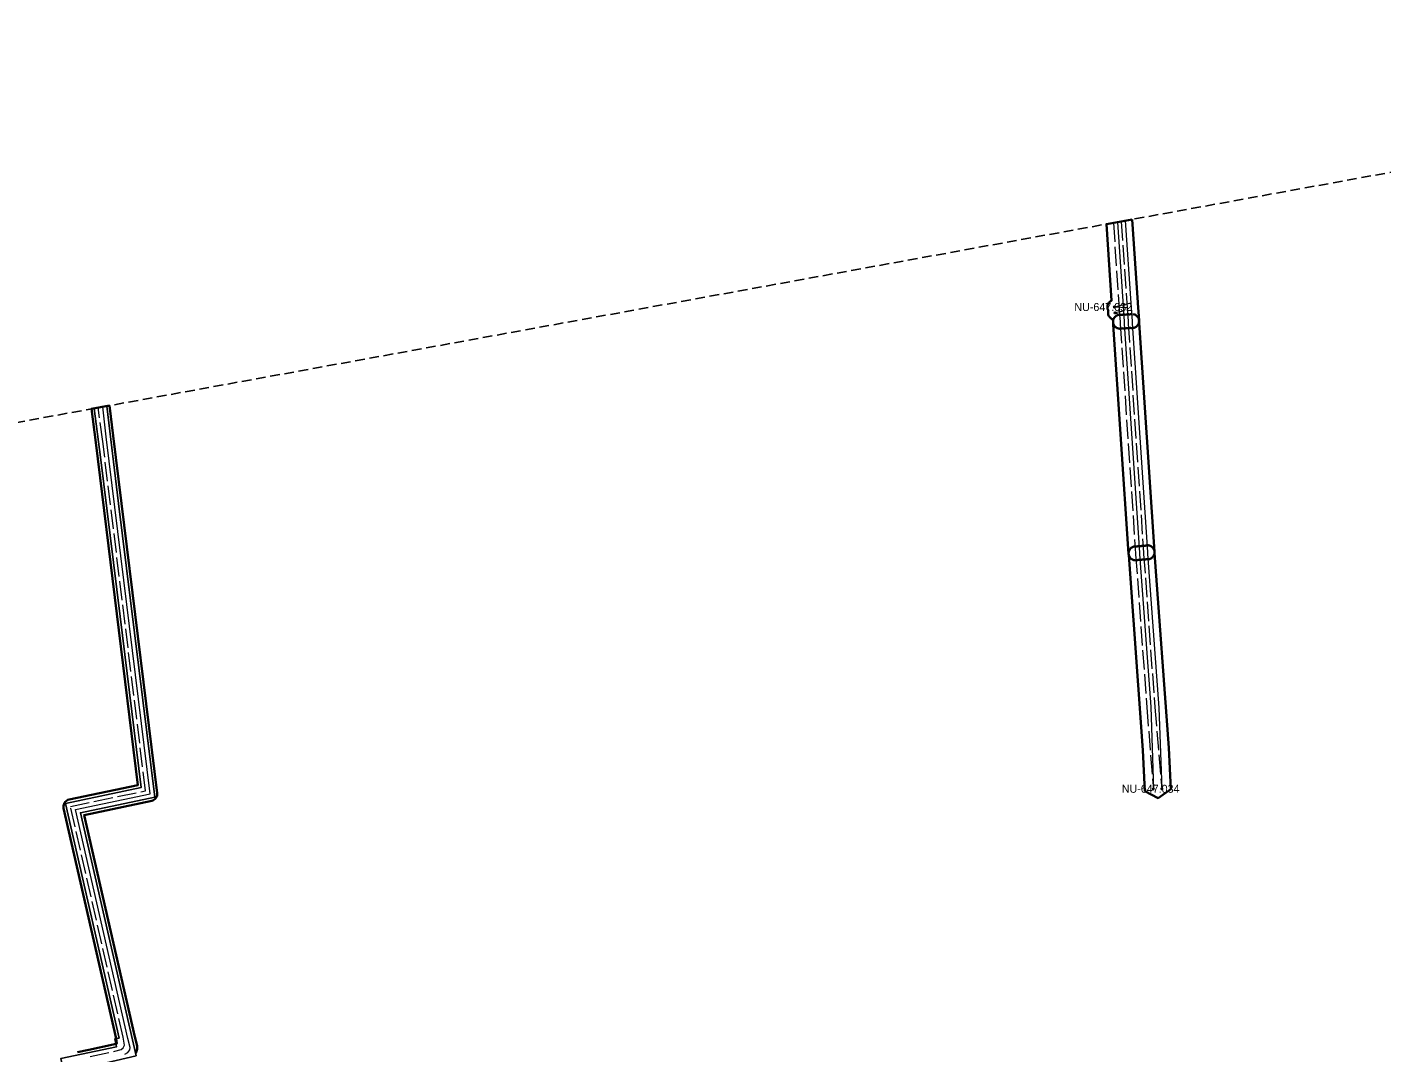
# Model space of a CAD drawing. Extents: x -452602 to -451136, y -1100088 to -1099653.
# Drawn here: x -451916.9 to -451781.4, y -1099858.1 to -1099755.5 of the extents above; entities that cross this region are included whole.
import ezdxf

# ---------------------------------------------------------------- set-up
doc = ezdxf.new("R2010")
doc.units = 0
doc.header["$LTSCALE"] = 0.32
doc.header["$PDMODE"] = 32
doc.header["$PDSIZE"] = 0.16
doc.linetypes.add('LONG_DASHED', pattern=[7.5, 6, -1.5])
doc.linetypes.add('MEDIUM_DASHED', pattern=[4.5, 3, -1.5])
for name, color, linetype, lineweight in [('2', 7, 'Continuous', 13), ('3', 7, 'Continuous', 25), ('62', 7, 'MEDIUM_DASHED', 25), ('8', 7, 'Continuous', 35)]:
    doc.layers.add(name, color=color, linetype=linetype, lineweight=lineweight)
doc.layers.add('4', color=7, linetype='Continuous')

msp = doc.modelspace()

# ---------------------------------------------------------------- linework, layer by layer
at = {"layer": '2', "linetype": 'LONG_DASHED'}
for p, q in [((-451808.262, -1099775.029), (-451807.645, -1099784.223)), ((-451807.469, -1099774.885), (-451806.889, -1099783.532)), ((-451806.889, -1099783.532), (-451808.164, -1099783.454)), ((-451806.889, -1099783.532), (-451806.798, -1099784.881)), ((-451807.645, -1099784.223), (-451808.094, -1099784.032)), ((-451807.645, -1099784.223), (-451807.598, -1099784.925)), ((-451804.925, -1099823.481), (-451804.268, -1099831.67)), ((-451804.124, -1099823.48), (-451803.421, -1099831.643))]:
    msp.add_line(p, q, dxfattribs=at)
at = {"layer": '2'}
for p, q in [((-451807.866, -1099774.957), (-451807.268, -1099783.874)), ((-451807.073, -1099774.813), (-451806.52, -1099783.061)), ((-451806.52, -1099783.061), (-451808.164, -1099783.454)), ((-451806.52, -1099783.061), (-451806.399, -1099784.861)), ((-451807.268, -1099783.874), (-451808.094, -1099784.032)), ((-451807.268, -1099783.874), (-451807.199, -1099784.903)), ((-451804.527, -1099823.448), (-451804.268, -1099831.67)), ((-451803.718, -1099823.551), (-451803.421, -1099831.643))]:
    msp.add_line(p, q, dxfattribs=at)
at = {"layer": '2', "linetype": 'LONG_DASHED'}
for points in [[(-451807.598, -1099784.925), (-451807.583, -1099785.149), (-451806.043, -1099808.094)], [(-451806.798, -1099784.881), (-451806.784, -1099785.096), (-451805.245, -1099808.024)], [(-451910.569, -1099858.433), (-451908.098, -1099857.907), (-451907.453, -1099857.73), (-451907.256, -1099857.548), (-451907.146, -1099857.285), (-451907.281, -1099856.503), (-451912.534, -1099833.415), (-451905.03, -1099831.839), (-451909.305, -1099796.918), (-451909.755, -1099793.518)], [(-451806.043, -1099808.094), (-451806.035, -1099808.217), (-451804.925, -1099823.481)], [(-451805.245, -1099808.024), (-451805.236, -1099808.16), (-451804.124, -1099823.48)]]:
    msp.add_lwpolyline(points, dxfattribs=at)
at = {"layer": '2'}
for points in [[(-451807.199, -1099784.903), (-451807.184, -1099785.122), (-451805.645, -1099808.059)], [(-451806.399, -1099784.861), (-451806.385, -1099785.068), (-451804.847, -1099807.989)], [(-451907.097, -1099858.2), (-451906.807, -1099858.025), (-451906.603, -1099857.741), (-451906.558, -1099857.538), (-451906.795, -1099856.611), (-451912.02, -1099833.732), (-451904.554, -1099832.158), (-451908.958, -1099796.423), (-451909.308, -1099793.436)], [(-451805.645, -1099808.059), (-451805.636, -1099808.188), (-451804.527, -1099823.448)], [(-451804.847, -1099807.989), (-451804.837, -1099808.133), (-451803.718, -1099823.551)]]:
    msp.add_lwpolyline(points, dxfattribs=at)
at = {"layer": '3'}
msp.add_lwpolyline([(-451904.636, -1099869.929), (-451904.863, -1099868.93), (-451906.412, -1099862.297), (-451906.981, -1099862.474), (-451907.181, -1099861.682), (-451912.537, -1099862.903), (-451913.505, -1099858.632), (-451907.928, -1099857.445), (-451908.108, -1099856.664), (-451907.674, -1099856.581), (-451913.014, -1099833.107), (-451905.472, -1099831.523), (-451907.565, -1099814.42), (-451909.516, -1099798.485), (-451910.152, -1099793.59), (-451908.893, -1099793.361), (-451907.732, -1099803.104), (-451904.112, -1099832.473), (-451911.54, -1099834.039), (-451905.974, -1099858.353), (-451911.404, -1099859.633), (-451911.089, -1099860.954), (-451905.594, -1099859.769), (-451903.412, -1099869.624)], close=True, dxfattribs=at)
at = {"layer": '4'}
for p in [(-451808.164, -1099783.454), (-451808.094, -1099784.032), (-451804.268, -1099831.67), (-451803.421, -1099831.643)]:
    msp.add_point(p, dxfattribs=at)
at = {"layer": '62'}
msp.add_lwpolyline([(-451137.485, -1099816.961), (-452572.169, -1100088.267), (-452602.314, -1099919.678), (-451137.485, -1099652.838), (-451136.368, -1099701.963)], close=True, dxfattribs=at)
at = {"layer": '8'}
msp.add_line((-451806.269, -1099784.173), (-451806.197, -1099784.19), dxfattribs=at)
for points in [[(-451806.38, -1099774.687), (-451805.824, -1099782.986), (-451805.822, -1099783.014), (-451805.819, -1099783.06), (-451805.7, -1099784.814), (-451805.699, -1099784.861), (-451805.703, -1099784.935), (-451805.715, -1099785.008), (-451805.734, -1099785.08), (-451805.761, -1099785.15), (-451805.796, -1099785.216), (-451805.837, -1099785.278), (-451805.884, -1099785.335), (-451805.938, -1099785.387), (-451805.996, -1099785.433), (-451806.06, -1099785.473), (-451806.127, -1099785.505), (-451806.197, -1099785.531), (-451806.269, -1099785.548), (-451806.343, -1099785.558), (-451806.417, -1099785.56), (-451806.492, -1099785.554), (-451806.565, -1099785.541), (-451806.596, -1099785.552), (-451806.668, -1099785.569), (-451806.742, -1099785.579), (-451806.816, -1099785.581), (-451806.891, -1099785.575), (-451806.964, -1099785.562), (-451806.997, -1099785.574), (-451807.069, -1099785.591), (-451807.143, -1099785.601), (-451807.217, -1099785.603), (-451807.292, -1099785.597), (-451807.365, -1099785.583), (-451807.396, -1099785.595), (-451807.468, -1099785.612), (-451807.542, -1099785.622), (-451807.616, -1099785.624), (-451807.691, -1099785.618), (-451807.764, -1099785.605), (-451807.835, -1099785.583), (-451807.904, -1099785.554), (-451807.969, -1099785.518), (-451808.03, -1099785.475), (-451808.086, -1099785.426), (-451808.137, -1099785.371), (-451808.181, -1099785.311), (-451808.219, -1099785.247), (-451808.25, -1099785.179), (-451808.273, -1099785.109), (-451808.289, -1099785.036), (-451808.296, -1099784.971), (-451808.314, -1099784.699), (-451808.368, -1099784.676), (-451808.401, -1099784.661), (-451808.466, -1099784.625), (-451808.527, -1099784.582), (-451808.583, -1099784.533), (-451808.633, -1099784.478), (-451808.678, -1099784.418), (-451808.716, -1099784.354), (-451808.746, -1099784.286), (-451808.77, -1099784.216), (-451808.786, -1099784.143), (-451808.793, -1099784.069), (-451808.793, -1099783.994), (-451808.786, -1099783.92), (-451808.77, -1099783.847), (-451808.761, -1099783.82), (-451808.786, -1099783.777), (-451808.816, -1099783.709), (-451808.84, -1099783.639), (-451808.856, -1099783.566), (-451808.864, -1099783.492), (-451808.864, -1099783.417), (-451808.856, -1099783.343), (-451808.84, -1099783.27), (-451808.816, -1099783.2), (-451808.786, -1099783.132), (-451808.748, -1099783.068), (-451808.703, -1099783.008), (-451808.653, -1099782.953), (-451808.597, -1099782.904), (-451808.536, -1099782.861), (-451808.471, -1099782.825), (-451808.441, -1099782.813), (-451808.955, -1099775.156)], [(-451802.725, -1099827.558), (-451802.506, -1099831.679), (-451803.792, -1099832.569), (-451805.109, -1099831.87), (-451805.315, -1099827.774), (-451806.733, -1099808.265), (-451806.741, -1099808.139), (-451806.742, -1099808.131), (-451806.742, -1099808.056), (-451806.734, -1099807.982), (-451806.718, -1099807.909), (-451806.695, -1099807.839), (-451806.664, -1099807.771), (-451806.626, -1099807.706), (-451806.582, -1099807.647), (-451806.531, -1099807.592), (-451806.475, -1099807.543), (-451806.414, -1099807.5), (-451806.349, -1099807.464), (-451806.28, -1099807.435), (-451806.209, -1099807.414), (-451806.136, -1099807.4), (-451806.061, -1099807.394), (-451805.987, -1099807.396), (-451805.913, -1099807.406), (-451805.901, -1099807.409), (-451805.882, -1099807.401), (-451805.811, -1099807.379), (-451805.738, -1099807.366), (-451805.663, -1099807.36), (-451805.589, -1099807.362), (-451805.515, -1099807.372), (-451805.503, -1099807.375), (-451805.482, -1099807.366), (-451805.411, -1099807.344), (-451805.338, -1099807.331), (-451805.263, -1099807.325), (-451805.189, -1099807.327), (-451805.115, -1099807.337), (-451805.104, -1099807.339), (-451805.084, -1099807.331), (-451805.013, -1099807.309), (-451804.94, -1099807.296), (-451804.865, -1099807.29), (-451804.791, -1099807.292), (-451804.717, -1099807.302), (-451804.645, -1099807.319), (-451804.575, -1099807.345), (-451804.508, -1099807.377), (-451804.444, -1099807.417), (-451804.386, -1099807.463), (-451804.332, -1099807.515), (-451804.285, -1099807.572), (-451804.244, -1099807.634), (-451804.209, -1099807.7), (-451804.182, -1099807.77), (-451804.163, -1099807.842), (-451804.151, -1099807.915), (-451804.148, -1099807.941), (-451804.139, -1099808.083)]]:
    msp.add_lwpolyline(points, close=True, dxfattribs=at)
for points in [[(-451806.197, -1099784.19), (-451806.127, -1099784.216), (-451806.06, -1099784.248), (-451805.996, -1099784.288), (-451805.938, -1099784.334), (-451805.884, -1099784.386), (-451805.837, -1099784.443), (-451805.796, -1099784.505), (-451805.761, -1099784.571), (-451805.734, -1099784.641), (-451805.715, -1099784.712), (-451805.703, -1099784.786), (-451805.7, -1099784.813), (-451805.686, -1099785.022), (-451804.148, -1099807.943), (-451804.147, -1099807.989), (-451804.151, -1099808.064), (-451804.163, -1099808.138), (-451804.182, -1099808.209), (-451804.209, -1099808.279), (-451804.244, -1099808.345), (-451804.285, -1099808.407), (-451804.332, -1099808.464), (-451804.386, -1099808.516), (-451804.444, -1099808.562), (-451804.508, -1099808.602), (-451804.575, -1099808.634), (-451804.645, -1099808.66), (-451804.717, -1099808.677), (-451804.791, -1099808.687), (-451804.865, -1099808.689), (-451804.94, -1099808.683), (-451804.987, -1099808.675), (-451805.043, -1099808.695), (-451805.115, -1099808.712), (-451805.189, -1099808.722), (-451805.263, -1099808.724), (-451805.338, -1099808.718), (-451805.386, -1099808.709), (-451805.443, -1099808.73), (-451805.515, -1099808.747), (-451805.589, -1099808.757), (-451805.663, -1099808.759), (-451805.738, -1099808.753), (-451805.786, -1099808.744), (-451805.841, -1099808.764), (-451805.913, -1099808.781), (-451805.987, -1099808.791), (-451806.061, -1099808.793), (-451806.136, -1099808.787), (-451806.209, -1099808.774), (-451806.28, -1099808.752), (-451806.349, -1099808.723), (-451806.414, -1099808.687), (-451806.475, -1099808.644), (-451806.531, -1099808.595), (-451806.582, -1099808.54), (-451806.626, -1099808.48), (-451806.664, -1099808.416), (-451806.695, -1099808.348), (-451806.718, -1099808.278), (-451806.734, -1099808.205), (-451806.741, -1099808.14), (-451808.281, -1099785.195), (-451808.296, -1099784.971), (-451808.297, -1099784.962), (-451808.297, -1099784.887), (-451808.289, -1099784.813), (-451808.273, -1099784.74), (-451808.25, -1099784.67), (-451808.219, -1099784.602), (-451808.181, -1099784.537), (-451808.137, -1099784.478), (-451808.086, -1099784.423), (-451808.03, -1099784.374), (-451807.969, -1099784.331), (-451807.904, -1099784.295), (-451807.835, -1099784.266), (-451807.764, -1099784.245), (-451807.691, -1099784.231), (-451807.616, -1099784.225), (-451807.542, -1099784.227), (-451807.468, -1099784.237), (-451807.436, -1099784.245), (-451807.365, -1099784.223), (-451807.292, -1099784.21), (-451807.217, -1099784.204), (-451807.143, -1099784.206), (-451807.069, -1099784.216), (-451807.036, -1099784.223), (-451806.964, -1099784.201), (-451806.891, -1099784.188), (-451806.816, -1099784.182), (-451806.742, -1099784.184), (-451806.668, -1099784.194), (-451806.636, -1099784.202), (-451806.565, -1099784.181), (-451806.492, -1099784.167), (-451806.417, -1099784.161), (-451806.343, -1099784.163)], [(-451911.844, -1099857.988), (-451911.822, -1099857.983), (-451910.714, -1099857.749), (-451908.264, -1099857.227), (-451907.884, -1099857.122), (-451907.968, -1099856.64), (-451913.217, -1099833.57), (-451913.233, -1099833.46), (-451913.231, -1099833.35), (-451913.212, -1099833.24), (-451913.176, -1099833.135), (-451913.123, -1099833.037), (-451913.056, -1099832.949), (-451912.976, -1099832.872), (-451912.885, -1099832.809), (-451912.784, -1099832.761), (-451912.678, -1099832.73), (-451905.803, -1099831.286), (-451910, -1099797.006), (-451910.445, -1099793.643), (-451908.618, -1099793.311)], [(-451908.618, -1099793.311), (-451908.263, -1099796.339), (-451903.86, -1099832.072), (-451903.855, -1099832.188), (-451903.869, -1099832.302), (-451903.902, -1099832.413), (-451903.953, -1099832.516), (-451904.02, -1099832.61), (-451904.102, -1099832.692), (-451904.196, -1099832.759), (-451904.299, -1099832.81), (-451904.41, -1099832.843), (-451911.179, -1099834.27), (-451906.115, -1099856.446), (-451905.88, -1099857.364), (-451905.861, -1099857.471), (-451905.859, -1099857.579), (-451905.874, -1099857.687), (-451905.919, -1099857.892), (-451905.946, -1099857.983), (-451905.984, -1099858.069)]]:
    msp.add_lwpolyline(points, dxfattribs=at)

# ---------------------------------------------------------------- texts
at = {"layer": '4'}
for s, p in [('NU-647.032', (-451812.164, -1099783.854)), ('NU-647.034', (-451807.421, -1099832.043))]:
    msp.add_text(s, height=0.8, dxfattribs=at).set_placement(p)

doc.saveas('drawing.dxf')
